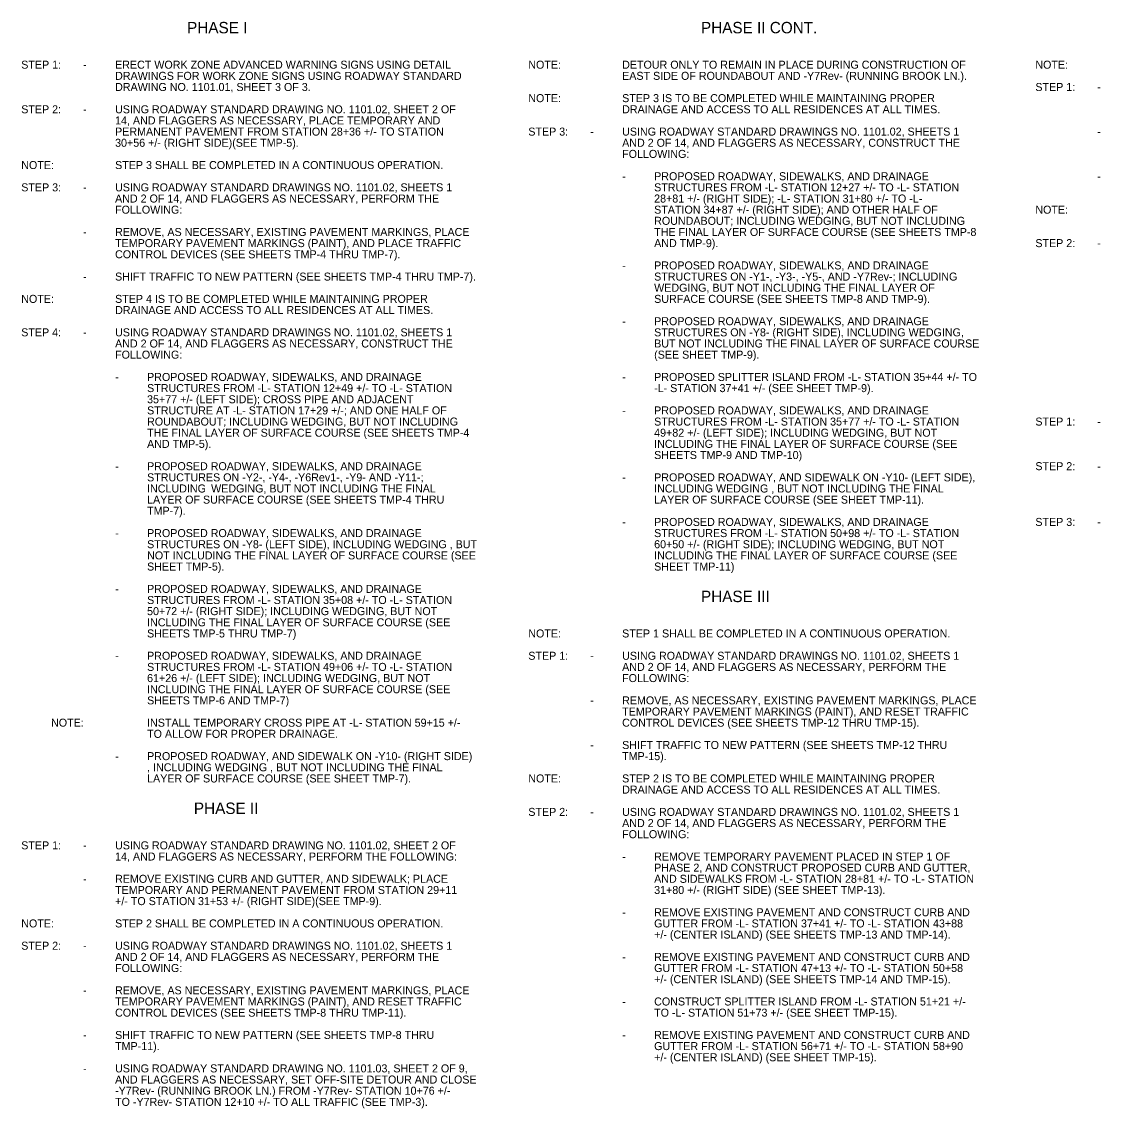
# Model space of a CAD drawing. Extents: x 764226 to 769781, y 650021 to 652521.
# Drawn here: x 764226 to 765169, y 651480 to 652431 of the extents above; entities that cross this region are included whole.
import ezdxf

# ---------------------------------------------------------------- set-up
doc = ezdxf.new("R2010")
doc.units = 0
doc.layers.add('Default', color=7, linetype='Continuous')

msp = doc.modelspace()

# ---------------------------------------------------------------- texts
at = {"layer": 'Default'}
for s, height, p in [('PHASE I', 10, (764370.21, 652420.38)), ('PHASE II CONT.', 10, (764819.77, 652420.38)), ('STEP 1:', 7, (764225.14, 652389.46)), ('-', 7, (764279.23, 652389.46)), ('ERECT WORK ZONE ADVANCED WARNING SIGNS USING DETAIL ', 7, (764307.23, 652389.46)), ('NOTE:', 7, (764668.71, 652389.46)), ('DETOUR ONLY TO REMAIN IN PLACE DURING CONSTRUCTION OF ', 7, (764750.81, 652389.46)), ('NOTE: ', 7, (765112.29, 652389.46)), ('DRAWINGS FOR WORK ZONE SIGNS USING ROADWAY STANDARD ', 7, (764307.23, 652379.71)), ('EAST SIDE OF ROUNDABOUT AND -Y7Rev- (RUNNING BROOK LN.).', 7, (764750.81, 652379.71)), ('DRAWING NO. 1101.01, SHEET 3 OF 3.', 7, (764307.23, 652369.95)), ('STEP 1:', 7, (765112.29, 652369.96)), ('-', 7, (765166.39, 652369.96)), ('NOTE: ', 7, (764668.71, 652360.2)), ('STEP 3 IS TO BE COMPLETED WHILE MAINTAINING PROPER ', 7, (764750.81, 652360.2)), ('STEP 2:', 7, (764225.14, 652350.45)), ('-', 7, (764279.23, 652350.45)), ('USING ROADWAY STANDARD DRAWING NO. 1101.02, SHEET 2 OF ', 7, (764307.23, 652350.45)), ('DRAINAGE AND ACCESS TO ALL RESIDENCES AT ALL TIMES.', 7, (764750.81, 652350.45)), ('14, AND FLAGGERS AS NECESSARY, PLACE TEMPORARY AND ', 7, (764307.23, 652340.69)), ('PERMANENT PAVEMENT FROM STATION 28+36 +/- TO STATION ', 7, (764307.23, 652330.94)), ('STEP 3:', 7, (764668.71, 652330.94)), ('-', 7, (764722.81, 652330.94)), ('USING ROADWAY STANDARD DRAWINGS NO. 1101.02, SHEETS 1 ', 7, (764750.81, 652330.94)), ('-', 7, (765166.39, 652330.94)), ('30+56 +/- (RIGHT SIDE)(SEE TMP-5).', 7, (764307.23, 652321.18)), ('AND 2 OF 14, AND FLAGGERS AS NECESSARY, CONSTRUCT THE ', 7, (764750.81, 652321.18)), ('FOLLOWING:', 7, (764750.81, 652311.43)), ('NOTE: ', 7, (764225.14, 652301.68)), ('STEP 3 SHALL BE COMPLETED IN A CONTINUOUS OPERATION.', 7, (764307.23, 652301.68)), ('PROPOSED ROADWAY, SIDEWALKS, AND DRAINAGE ', 7, (764778.81, 652291.92)), ('STEP 3:', 7, (764225.14, 652282.17)), ('USING ROADWAY STANDARD DRAWINGS NO. 1101.02, SHEETS 1 ', 7, (764307.23, 652282.17)), ('-', 7, (764750.81, 652291.92)), ('STRUCTURES FROM -L- STATION 12+27 +/- TO -L- STATION ', 7, (764778.81, 652282.17)), ('-', 7, (765166.39, 652291.92)), ('-', 7, (764279.23, 652282.17)), ('AND 2 OF 14, AND FLAGGERS AS NECESSARY, PERFORM THE ', 7, (764307.23, 652272.41)), ('28+81 +/- (RIGHT SIDE); -L- STATION 31+80 +/- TO -L- ', 7, (764778.81, 652272.41)), ('FOLLOWING:', 7, (764307.23, 652262.66)), ('STATION 34+87 +/- (RIGHT SIDE); AND OTHER HALF OF ', 7, (764778.81, 652262.66)), ('NOTE: ', 7, (765112.29, 652262.66)), ('ROUNDABOUT; INCLUDING WEDGING, BUT NOT INCLUDING ', 7, (764778.81, 652252.91)), ('REMOVE, AS NECESSARY, EXISTING PAVEMENT MARKINGS, PLACE ', 7, (764307.23, 652243.15)), ('THE FINAL LAYER OF SURFACE COURSE (SEE SHEETS TMP-8 ', 7, (764778.81, 652243.15)), ('-', 7, (764279.23, 652243.15)), ('TEMPORARY PAVEMENT MARKINGS (PAINT), AND PLACE TRAFFIC ', 7, (764307.23, 652233.4)), ('AND TMP-9). ', 7, (764778.81, 652233.4)), ('STEP 2:', 7, (765112.29, 652233.4)), ('CONTROL DEVICES (SEE SHEETS TMP-4 THRU TMP-7).', 7, (764307.23, 652223.64)), ('-', 7, (765166.39, 652233.4)), ('PROPOSED ROADWAY, SIDEWALKS, AND DRAINAGE ', 7, (764778.81, 652213.89)), ('SHIFT TRAFFIC TO NEW PATTERN (SEE SHEETS TMP-4 THRU TMP-7).', 7, (764307.23, 652204.14)), ('-', 7, (764750.81, 652213.89)), ('STRUCTURES ON -Y1-, -Y3-, -Y5-, AND -Y7Rev-; INCLUDING ', 7, (764778.81, 652204.14)), ('-', 7, (764279.23, 652204.14)), ('WEDGING, BUT NOT INCLUDING THE FINAL LAYER OF ', 7, (764778.81, 652194.38)), ('NOTE: ', 7, (764225.13, 652184.63)), ('STEP 4 IS TO BE COMPLETED WHILE MAINTAINING PROPER ', 7, (764307.23, 652184.63)), ('SURFACE COURSE (SEE SHEETS TMP-8 AND TMP-9).', 7, (764778.81, 652184.63)), ('DRAINAGE AND ACCESS TO ALL RESIDENCES AT ALL TIMES.', 7, (764307.23, 652174.87)), ('PROPOSED ROADWAY, SIDEWALKS, AND DRAINAGE', 7, (764778.81, 652165.12)), ('-', 7, (764750.81, 652165.12)), ('STRUCTURES ON -Y8- (RIGHT SIDE), INCLUDING WEDGING, ', 7, (764778.81, 652155.37)), ('STEP 4:', 7, (764225.13, 652155.37)), ('-', 7, (764279.23, 652155.37)), ('USING ROADWAY STANDARD DRAWINGS NO. 1101.02, SHEETS 1 ', 7, (764307.23, 652155.37)), ('AND 2 OF 14, AND FLAGGERS AS NECESSARY, CONSTRUCT THE ', 7, (764307.23, 652145.61)), ('BUT NOT INCLUDING THE FINAL LAYER OF SURFACE COURSE ', 7, (764778.81, 652145.61)), ('FOLLOWING:', 7, (764307.23, 652135.86)), ('(SEE SHEET TMP-9).', 7, (764778.81, 652135.86)), ('-', 7, (764307.23, 652116.35)), ('PROPOSED ROADWAY, SIDEWALKS, AND DRAINAGE ', 7, (764335.23, 652116.35)), ('-', 7, (764750.81, 652116.35)), ('PROPOSED SPLITTER ISLAND FROM -L- STATION 35+44 +/- TO ', 7, (764778.81, 652116.35)), ('STRUCTURES FROM -L- STATION 12+49 +/- TO -L- STATION ', 7, (764335.23, 652106.6)), ('-L- STATION 37+41 +/- (SEE SHEET TMP-9).', 7, (764778.81, 652106.6)), ('35+77 +/- (LEFT SIDE); CROSS PIPE AND ADJACENT ', 7, (764335.23, 652096.84)), ('STRUCTURE AT -L- STATION 17+29 +/-; AND ONE HALF OF ', 7, (764335.23, 652087.09)), ('-', 7, (764750.81, 652087.09)), ('PROPOSED ROADWAY, SIDEWALKS, AND DRAINAGE', 7, (764778.81, 652087.09)), ('ROUNDABOUT; INCLUDING WEDGING, BUT NOT INCLUDING ', 7, (764335.23, 652077.33)), ('STRUCTURES FROM -L- STATION 35+77 +/- TO -L- STATION', 7, (764778.81, 652077.33)), ('STEP 1:', 7, (765112.29, 652077.33)), ('-', 7, (765166.39, 652077.33)), ('THE FINAL LAYER OF SURFACE COURSE (SEE SHEETS TMP-4 ', 7, (764335.23, 652067.58)), ('49+82 +/- (LEFT SIDE); INCLUDING WEDGING, BUT NOT ', 7, (764778.81, 652067.58)), ('AND TMP-5). ', 7, (764335.23, 652057.83)), ('INCLUDING THE FINAL LAYER OF SURFACE COURSE (SEE ', 7, (764778.81, 652057.83)), ('SHEETS TMP-9 AND TMP-10)', 7, (764778.81, 652048.07)), ('-', 7, (764307.23, 652038.32)), ('PROPOSED ROADWAY, SIDEWALKS, AND DRAINAGE ', 7, (764335.23, 652038.32)), ('STEP 2:', 7, (765112.29, 652038.32)), ('-', 7, (765166.39, 652038.32)), ('STRUCTURES ON -Y2-, -Y4-, -Y6Rev1-, -Y9- AND -Y11-; ', 7, (764335.23, 652028.56)), ('-', 7, (764750.81, 652028.56)), ('PROPOSED ROADWAY, AND SIDEWALK ON -Y10- (LEFT SIDE), ', 7, (764778.81, 652028.56)), ('INCLUDING ', 7, (764335.23, 652018.81)), ('WEDGING, BUT NOT INCLUDING THE FINAL ', 7, (764391.23, 652018.81)), ('INCLUDING WEDGING , BUT NOT INCLUDING THE FINAL ', 7, (764778.81, 652018.81)), ('LAYER OF SURFACE COURSE (SEE SHEETS TMP-4 THRU ', 7, (764335.23, 652009.06)), ('LAYER OF SURFACE COURSE (SEE SHEET TMP-11).', 7, (764778.81, 652009.06)), ('TMP-7).', 7, (764335.23, 651999.3)), ('-', 7, (764750.81, 651989.55)), ('PROPOSED ROADWAY, SIDEWALKS, AND DRAINAGE ', 7, (764778.81, 651989.55)), ('STEP 3:', 7, (765112.29, 651989.55)), ('-', 7, (765166.39, 651989.55)), ('-', 7, (764307.23, 651979.79)), ('PROPOSED ROADWAY, SIDEWALKS, AND DRAINAGE', 7, (764335.23, 651979.79)), ('STRUCTURES FROM -L- STATION 50+98 +/- TO -L- STATION ', 7, (764778.81, 651979.79)), ('STRUCTURES ON -Y8- (LEFT SIDE), INCLUDING WEDGING , BUT ', 7, (764335.23, 651970.04)), ('60+50 +/- (RIGHT SIDE); INCLUDING WEDGING, BUT NOT ', 7, (764778.81, 651970.04)), ('NOT INCLUDING THE FINAL LAYER OF SURFACE COURSE (SEE ', 7, (764335.23, 651960.29)), ('INCLUDING THE FINAL LAYER OF SURFACE COURSE (SEE ', 7, (764778.81, 651960.29)), ('SHEET TMP-5).', 7, (764335.23, 651950.53)), ('SHEET TMP-11)', 7, (764778.81, 651950.53)), ('PROPOSED ROADWAY, SIDEWALKS, AND DRAINAGE', 7, (764335.23, 651931.02)), ('-', 7, (764307.23, 651931.02)), ('STRUCTURES FROM -L- STATION 35+08 +/- TO -L- STATION', 7, (764335.23, 651921.27)), ('PHASE III', 10, (764819.77, 651922.93)), ('50+72 +/- (RIGHT SIDE); INCLUDING WEDGING, BUT NOT ', 7, (764335.23, 651911.52)), ('INCLUDING THE FINAL LAYER OF SURFACE COURSE (SEE ', 7, (764335.23, 651901.76)), ('SHEETS TMP-5 THRU TMP-7)', 7, (764335.23, 651892.01)), ('NOTE: ', 7, (764668.71, 651892.01)), ('STEP 1 SHALL BE COMPLETED IN A CONTINUOUS OPERATION.', 7, (764750.81, 651892.01)), ('PROPOSED ROADWAY, SIDEWALKS, AND DRAINAGE ', 7, (764335.23, 651872.5)), ('STEP 1:', 7, (764668.71, 651872.5)), ('USING ROADWAY STANDARD DRAWINGS NO. 1101.02, SHEETS 1 ', 7, (764750.81, 651872.5)), ('-', 7, (764307.23, 651872.5)), ('STRUCTURES FROM -L- STATION 49+06 +/- TO -L- STATION ', 7, (764335.23, 651862.75)), ('-', 7, (764722.81, 651872.5)), ('AND 2 OF 14, AND FLAGGERS AS NECESSARY, PERFORM THE ', 7, (764750.8, 651862.75)), ('61+26 +/- (LEFT SIDE); INCLUDING WEDGING, BUT NOT ', 7, (764335.23, 651852.99)), ('FOLLOWING:', 7, (764750.8, 651852.99)), ('INCLUDING THE FINAL LAYER OF SURFACE COURSE (SEE ', 7, (764335.23, 651843.24)), ('SHEETS TMP-6 AND TMP-7)', 7, (764335.23, 651833.48)), ('REMOVE, AS NECESSARY, EXISTING PAVEMENT MARKINGS, PLACE ', 7, (764750.8, 651833.48)), ('-', 7, (764722.81, 651833.48)), ('TEMPORARY PAVEMENT MARKINGS (PAINT), AND RESET TRAFFIC ', 7, (764750.8, 651823.73)), ('NOTE:', 7, (764251.23, 651813.98)), ('INSTALL TEMPORARY CROSS PIPE AT -L- STATION 59+15 +/- ', 7, (764335.23, 651813.98)), ('CONTROL DEVICES (SEE SHEETS TMP-12 THRU TMP-15).', 7, (764750.8, 651813.98)), ('TO ALLOW FOR PROPER DRAINAGE.', 7, (764335.23, 651804.22)), ('SHIFT TRAFFIC TO NEW PATTERN (SEE SHEETS TMP-12 THRU ', 7, (764750.8, 651794.47)), ('PROPOSED ROADWAY, AND SIDEWALK ON -Y10- (RIGHT SIDE)', 7, (764335.23, 651784.71)), ('-', 7, (764722.81, 651794.47)), ('TMP-15).', 7, (764750.8, 651784.71)), ('-', 7, (764307.23, 651784.71)), (', INCLUDING WEDGING , BUT NOT INCLUDING THE FINAL ', 7, (764335.23, 651774.96)), ('LAYER OF SURFACE COURSE (SEE SHEET TMP-7).', 7, (764335.23, 651765.2)), ('NOTE: ', 7, (764668.71, 651765.21)), ('STEP 2 IS TO BE COMPLETED WHILE MAINTAINING PROPER ', 7, (764750.8, 651765.21)), ('DRAINAGE AND ACCESS TO ALL RESIDENCES AT ALL TIMES.', 7, (764750.8, 651755.45)), ('PHASE II', 10, (764376.19, 651737.6)), ('STEP 2:', 7, (764668.71, 651735.94)), ('-', 7, (764722.81, 651735.94)), ('USING ROADWAY STANDARD DRAWINGS NO. 1101.02, SHEETS 1 ', 7, (764750.8, 651735.94)), ('AND 2 OF 14, AND FLAGGERS AS NECESSARY, PERFORM THE ', 7, (764750.8, 651726.19)), ('FOLLOWING:', 7, (764750.8, 651716.44)), ('STEP 1:', 7, (764225.13, 651706.68)), ('-', 7, (764279.23, 651706.68)), ('USING ROADWAY STANDARD DRAWING NO. 1101.02, SHEET 2 OF ', 7, (764307.23, 651706.68)), ('14, AND FLAGGERS AS NECESSARY, PERFORM THE FOLLOWING:', 7, (764307.23, 651696.93)), ('-', 7, (764750.8, 651696.93)), ('REMOVE TEMPORARY PAVEMENT PLACED IN STEP 1 OF ', 7, (764778.81, 651696.93)), ('PHASE 2, AND CONSTRUCT PROPOSED CURB AND GUTTER, ', 7, (764778.81, 651687.17)), ('-', 7, (764279.23, 651677.42)), ('REMOVE EXISTING CURB AND GUTTER, AND SIDEWALK; PLACE ', 7, (764307.23, 651677.42)), ('AND SIDEWALKS FROM -L- STATION 28+81 +/- TO -L- STATION ', 7, (764778.81, 651677.42)), ('TEMPORARY AND PERMANENT PAVEMENT FROM STATION 29+11 ', 7, (764307.23, 651667.66)), ('31+80 +/- (RIGHT SIDE) (SEE SHEET TMP-13). ', 7, (764778.81, 651667.66)), ('+/- TO STATION 31+53 +/- (RIGHT SIDE)(SEE TMP-9).', 7, (764307.23, 651657.91)), ('-', 7, (764750.8, 651648.16)), ('REMOVE EXISTING PAVEMENT AND CONSTRUCT CURB AND ', 7, (764778.81, 651648.16)), ('NOTE: ', 7, (764225.13, 651638.4)), ('STEP 2 SHALL BE COMPLETED IN A CONTINUOUS OPERATION.', 7, (764307.23, 651638.4)), ('GUTTER FROM -L- STATION 37+41 +/- TO -L- STATION 43+88 ', 7, (764778.81, 651638.4)), ('+/- (CENTER ISLAND) (SEE SHEETS TMP-13 AND TMP-14).', 7, (764778.81, 651628.65)), ('STEP 2:', 7, (764225.13, 651618.89)), ('-', 7, (764279.23, 651618.89)), ('USING ROADWAY STANDARD DRAWINGS NO. 1101.02, SHEETS 1 ', 7, (764307.23, 651618.89)), ('AND 2 OF 14, AND FLAGGERS AS NECESSARY, PERFORM THE ', 7, (764307.23, 651609.14)), ('-', 7, (764750.8, 651609.14)), ('REMOVE EXISTING PAVEMENT AND CONSTRUCT CURB AND ', 7, (764778.81, 651609.14)), ('FOLLOWING:', 7, (764307.23, 651599.39)), ('GUTTER FROM -L- STATION 47+13 +/- TO -L- STATION 50+58 ', 7, (764778.81, 651599.39)), ('+/- (CENTER ISLAND) (SEE SHEETS TMP-14 AND TMP-15).', 7, (764778.81, 651589.63)), ('-', 7, (764279.23, 651579.88)), ('REMOVE, AS NECESSARY, EXISTING PAVEMENT MARKINGS, PLACE ', 7, (764307.23, 651579.88)), ('TEMPORARY PAVEMENT MARKINGS (PAINT), AND RESET TRAFFIC ', 7, (764307.23, 651570.12)), ('CONSTRUCT SPLITTER ISLAND FROM -L- STATION 51+21 +/- ', 7, (764778.81, 651570.12)), ('CONTROL DEVICES (SEE SHEETS TMP-8 THRU TMP-11).', 7, (764307.23, 651560.37)), ('-', 7, (764750.8, 651570.12)), ('TO -L- STATION 51+73 +/- (SEE SHEET TMP-15).', 7, (764778.81, 651560.37)), ('SHIFT TRAFFIC TO NEW PATTERN (SEE SHEETS TMP-8 THRU ', 7, (764307.23, 651540.86)), ('REMOVE EXISTING PAVEMENT AND CONSTRUCT CURB AND ', 7, (764778.81, 651540.86)), ('-', 7, (764279.23, 651540.86)), ('TMP-11).', 7, (764307.23, 651531.11)), ('-', 7, (764750.8, 651540.86)), ('GUTTER FROM -L- STATION 56+71 +/- TO -L- STATION 58+90 ', 7, (764778.81, 651531.11)), ('+/- (CENTER ISLAND) (SEE SHEET TMP-15).', 7, (764778.81, 651521.35)), ('USING ROADWAY STANDARD DRAWING NO. 1101.03, SHEET 2 OF 9, ', 7, (764307.23, 651511.6)), ('-', 7, (764279.23, 651511.6)), ('AND FLAGGERS AS NECESSARY, SET OFF-SITE DETOUR AND CLOSE ', 7, (764307.23, 651501.85)), ('-Y7Rev- (RUNNING BROOK LN.) FROM -Y7Rev- STATION 10+76 +/- ', 7, (764307.23, 651492.09)), ('TO -Y7Rev- STATION 12+10 +/- TO ALL TRAFFIC (SEE TMP-3).', 7, (764307.23, 651482.34))]:
    msp.add_text(s, height=height, rotation=359.99991, dxfattribs=at).set_placement(p)

doc.saveas('drawing.dxf')
